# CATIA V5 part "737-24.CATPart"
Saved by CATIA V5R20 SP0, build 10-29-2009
Part number: 737-24
Definition: NONE
Nomenclature: 737-24
Source: Unknown
Description: 737-24
Bounding box of the stored display mesh (mm): x -31.5 to 23, y -31.46 to 31.46, z -37 to 25
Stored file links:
  C:\Users\Utente\Desktop\IO LAVORO\3D X SITO CF\X SITO\737\737-24.CATPart
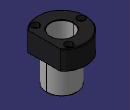
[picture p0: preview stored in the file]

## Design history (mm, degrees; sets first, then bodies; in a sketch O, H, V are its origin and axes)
Body1 "737-24" (main body)
  Solid1: solid without history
